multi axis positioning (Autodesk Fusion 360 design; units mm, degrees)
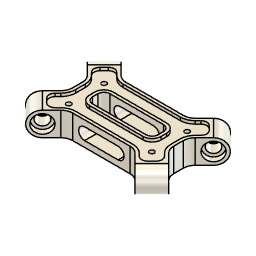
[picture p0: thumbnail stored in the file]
base_feature "Base Feature1" bodies "Screw", "Pull Stud", "Base", "Pull Stud (1)", "Pull Stud (2)", "Pull Stud (3)"
base_feature "Base Feature1"
base_feature "Base Feature1"
as_built_joint "As-built1"
as_built_joint "As-built4"
as_built_joint "As-built2" OffsetX 0 OffsetY 0 OffsetZ 0 AngleZ 0 DistanceMinimum 0
as_built_joint "As-built3" OffsetX 0 OffsetY 0 OffsetZ 0 AngleZ 0 DistanceMinimum 0
motion_link "MotionLink1" Value1 10 Value2 10
sketch "Stock Top Profile" plane through (0, 0, 0) normal (0, 1, 0) x axis (1, 0, 0)
  line L1 (-76.2, -12.7) -> (76.2, -12.7)
  line L2 (-76.2, 12.7) -> (-76.2, -12.7)
  line L3 (76.2, 12.7) -> (-76.2, 12.7)
  line L4 (76.2, -12.7) -> (76.2, 12.7)
  line L5 (-76.2, 12.7) -> (76.2, -12.7)
  line L6 (76.2, 12.7) -> (-76.2, -12.7)
  point P6 (0, 0)
  point P1 (0, 0)
  point P4 (-76.2, 12.7)
  point P5 (76.2, 12.7)
  point P3 (-76.2, -12.7)
  perpendicular L1 L2
  parallel L1 L3
  parallel L2 L4
  horizontal L1
  coincident L5 P6
  coincident L6 P6
  coincident P1 P6
  dimension "d13" distance P4 P5 = 152.4
  dimension "d14" distance P3 P4 = 25.4
  dimension "d21" OffsetX = 0
  dimension "d22" OffsetY = 0
  dimension "d23" OffsetZ = 0
  dimension "d24" AngleZ = 0
  dimension "d172" OffsetX = 0
  dimension "d173" OffsetY = 0
  dimension "d174" OffsetZ = 0
  dimension "d175" AngleZ = 0
  dimension "d188" OffsetX = 0
  dimension "d189" OffsetY = 0
  dimension "d190" OffsetZ = 0
  dimension "d191" AngleZ = 0
  dimension "d218" OffsetX = 0
  dimension "d219" OffsetY = 0
  dimension "d220" OffsetZ = 0
  dimension "d221" AngleZ = 0
  dimension "d238" OffsetX = 0
  dimension "d239" OffsetY = 0
  dimension "d240" OffsetZ = 0
  dimension "d241" AngleZ = 0
  dimension "d270" OffsetX = 0
  dimension "d271" OffsetY = 0
  dimension "d272" OffsetZ = 0
  dimension "d273" AngleZ = 0
extrude "Extrude1" new body sketch "Stock Top Profile" profile of L1 L2 L3 L4 along normal blind 38.1
sketch "Sketch1" plane through (0, 0, 25.6902) normal (0, 0, 1) x axis (1, 0, 0)
  line L1 (-62.3, 41.746) -> (-62.3, 43.3968)
  line L2 (62.3, 41.746) -> (-62.3, 41.746)
  line L3 (62.3, 43.3968) -> (62.3, 41.746)
  line L4 (-62.3, 43.3968) -> (62.3, 43.3968)
  line L5 (0, 40.3968) -> (0, 43.3968)
  line L6 (-62.3, 40.3968) -> (62.3, 40.3968)
  point P6 (0, 43.3968)
  point P7 (0, 40.3968)
  midpoint L4 P6
  perpendicular L2 L5
  coincident P7 L6
joint_origin "JointOrigin1" OffsetX 0 OffsetY 0 OffsetZ 0 AngleZ 0
joint "Assemble1" alignAngle 0 alignOffsetX 0 alignOffsetY 0 alignOffsetZ 0
joint "Assemble3" alignAngle 0 alignOffsetX 0 alignOffsetY 0 alignOffsetZ 0
sketch "Step Profile" plane through (76.2, 0, 0) normal (1, 0, 0) x axis (0, 0, -1)
  line L1 (12.7, 0) -> (-12.7, 0)
  line L2 (12.7, 38.1) -> (12.7, 0)
  line L3 (-12.7, 38.1) -> (12.7, 38.1)
  line L4 (-12.7, 0) -> (-12.7, 38.1)
  line L5 (-50.8, 38.1) -> (50.8, 38.1)
  line L6 (-50.8, 6.731) -> (-50.8, 38.1)
  line L7 (50.8, 6.731) -> (-50.8, 6.731)
  line L8 (50.8, 38.1) -> (50.8, 6.731)
  line L9 (-50.8, 6.731) -> (50.8, 38.1)
  line L10 (50.8, 6.731) -> (-50.8, 38.1)
  point P10 (0, 22.4155)
  point P1 (0, 0)
  point P6 (50.8, 38.1)
  point P7 (-50.8, 38.1)
  perpendicular L5 L6
  parallel L5 L7
  parallel L6 L8
  horizontal L5
  coincident L9 P10
  coincident L10 P10
  vertical P1 P10
  collinear L3 L5
  dimension "d184" distance P6 P7 = 101.6
  dimension "d185" distance L1 L7 = 6.731
extrude "Extrude2" add sketch "Step Profile" profile of L2 L4 L5 L6 L7 L8 to an object
copy_paste "CutPaste1"
copy_paste "CutPaste2"
copy_paste "CutPaste3"
copy_paste "CutPaste4"
as_built_joint "As-built5"
base_feature "Base Feature1"
joint "Assemble4" alignAngle 0 alignOffsetX 0 alignOffsetY 0 alignOffsetZ 0
copy_paste "CutPaste5"
base_feature "Base Feature1"
base_feature "Base Feature1" bodies "Pull Stud (1)", "Pull Stud (2)", "Base", "Screw", "Pull Stud (3)", "Pull Stud"
base_feature "Base Feature1"
base_feature "Base Feature1" bodies "Body1"
sketch "Sketch1" plane through (0, 85.85, 0) normal (0, 1, 0) x axis (-1, 0, 0)
  line L1 (62.3776, 12.3492) -> (-62.2224, 12.3492)
  line L2 (62.3776, 14) -> (62.3776, 12.3492)
  line L3 (-62.2224, 14) -> (62.3776, 14)
  line L4 (-62.2224, 12.3492) -> (-62.2224, 14)
  line L5 (62.3776, 11) -> (-62.2224, 11)
  line L6 (62.3776, 3) -> (-62.2224, 3)
joint_origin "JointOrigin1" OffsetX 0 named "d5_1" OffsetY 0 named "d6_1" OffsetZ 0 named "d7_1" AngleZ 0 named "d8_1"
joint_origin "JointOrigin2" OffsetX 0 named "d9_1" OffsetY 0 named "d10_1" OffsetZ 0 named "d11_1" AngleZ 0 named "d12_1"
copy_paste "CopyPaste1"
as_built_joint "As-built1"
as_built_joint "As-built2"
as_built_joint "As-built3" OffsetX 0 named "d13_1" OffsetY 0 named "d14_1" OffsetZ 0 named "d15_1" AngleZ 0 named "d16_1"
as_built_joint "As-built4" OffsetX 0 named "d17_1" OffsetY 0 named "d18_1" OffsetZ 0 named "d19_1" AngleZ 0 named "d20_1"
motion_link "MotionLink1" Value1 10 named "d21_1" Value2 10 named "d22_1"
sketch "Sketch1" plane through (0, 0, 0) normal (0, 1, 0) x axis (1, 0, 0)
  line L1 (-95.25, -50.8) -> (95.25, -50.8)
  line L2 (-95.25, 50.8) -> (-95.25, -50.8)
  line L3 (95.25, 50.8) -> (-95.25, 50.8)
  line L4 (95.25, -50.8) -> (95.25, 50.8)
  line L5 (-95.25, 50.8) -> (95.25, -50.8)
  line L6 (95.25, 50.8) -> (-95.25, -50.8)
  point P6 (0, 0)
  point P1 (0, 0)
  point P4 (-95.25, 50.8)
  point P5 (95.25, 50.8)
  point P3 (-95.25, -50.8)
  perpendicular L1 L2
  parallel L1 L3
  parallel L2 L4
  horizontal L1
  coincident L5 P6
  coincident L6 P6
  coincident P1 P6
  dimension "d23_1" distance P4 P5 = 190.5
  dimension "d24_1" distance P3 P4 = 101.6
extrude "Extrude1" new body sketch "Sketch1" profile of L1 L2 L3 L4 along normal blind 50.8 named "d25_1"
position "Position2"
joint "Assemble1" alignAngle 180 alignOffsetX 0 alignOffsetY 0 alignOffsetZ 0
joint "Assemble2" alignAngle 0 alignOffsetX 0 alignOffsetY 0 named "d41_1" alignOffsetZ 0 named "d42_1"
joint "Assemble10" OffsetX 0 OffsetY 0 OffsetZ 0 AngleZ 0 alignAngle 0 alignOffsetX 0 alignOffsetY 0 alignOffsetZ 0
sketch "Stock Top Profile" plane through (0, 0, 0) normal (0, 1, 0) x axis (1, 0, 0)
  line L1 (-76.2, -12.7) -> (76.2, -12.7)
  line L2 (-76.2, 12.7) -> (-76.2, -12.7)
  line L3 (76.2, 12.7) -> (-76.2, 12.7)
  line L4 (76.2, -12.7) -> (76.2, 12.7)
  line L5 (-76.2, 12.7) -> (76.2, -12.7)
  line L6 (76.2, 12.7) -> (-76.2, -12.7)
  point P6 (0, 0)
  point P1 (0, 0)
  point P4 (-76.2, 12.7)
  point P5 (76.2, 12.7)
  point P3 (-76.2, -12.7)
  perpendicular L1 L2
  parallel L1 L3
  parallel L2 L4
  horizontal L1
  coincident L5 P6
  coincident L6 P6
  coincident P1 P6
  dimension "d13_2" distance P4 P5 = 152.4
  dimension "d14_2" distance P3 P4 = 25.4
  dimension "d21_2" OffsetX = 0
  dimension "d22_2" OffsetY = 0
  dimension "d23_2" OffsetZ = 0
  dimension "d24_2" AngleZ = 0
  dimension "d172_1" OffsetX = 0
  dimension "d173_1" OffsetY = 0
  dimension "d174_1" OffsetZ = 0
  dimension "d175_1" AngleZ = 0
  dimension "d188_1" OffsetX = 0
  dimension "d189_1" OffsetY = 0
  dimension "d190_1" OffsetZ = 0
  dimension "d191_1" AngleZ = 0
  dimension "d218_1" OffsetX = 0
  dimension "d219_1" OffsetY = 0
  dimension "d220_1" OffsetZ = 0
  dimension "d221_1" AngleZ = 0
  dimension "d238_1" OffsetX = 0
  dimension "d239_1" OffsetY = 0
  dimension "d240_1" OffsetZ = 0
  dimension "d241_1" AngleZ = 0
  dimension "d270_1" OffsetX = 0
  dimension "d271_1" OffsetY = 0
  dimension "d272_1" OffsetZ = 0
  dimension "d273_1" AngleZ = 0
extrude "Extrude1" new body sketch "Stock Top Profile" profile of L1 L2 L3 L4 along normal blind 38.1 named "d15_2"
position "Position4"
position "Position5"
joint_origin "JointOrigin3" OffsetX 0 named "d41_2" OffsetY 0 named "d42_2" OffsetZ 0 named "d43_1" AngleZ 0 named "d44_1"
joint_origin "JointOrigin4" OffsetX 0 named "d49_1" OffsetY 0 named "d50_1" OffsetZ 0 named "d51_1" AngleZ 0 named "d52_1"
sketch "Step Profile" plane through (76.2, 0, 0) normal (1, 0, 0) x axis (0, 0, -1)
  line L1 (12.7, 0) -> (-12.7, 0)
  line L2 (12.7, 38.1) -> (12.7, 0)
  line L3 (-12.7, 38.1) -> (12.7, 38.1)
  line L4 (-12.7, 0) -> (-12.7, 38.1)
  line L5 (-50.8, 38.1) -> (50.8, 38.1)
  line L6 (-50.8, 6.731) -> (-50.8, 38.1)
  line L7 (50.8, 6.731) -> (-50.8, 6.731)
  line L8 (50.8, 38.1) -> (50.8, 6.731)
  line L9 (-50.8, 6.731) -> (50.8, 38.1)
  line L10 (50.8, 6.731) -> (-50.8, 38.1)
  point P10 (0, 22.4155)
  point P1 (0, 0)
  point P6 (50.8, 38.1)
  point P7 (-50.8, 38.1)
  perpendicular L5 L6
  parallel L5 L7
  parallel L6 L8
  horizontal L5
  coincident L9 P10
  coincident L10 P10
  vertical P1 P10
  collinear L3 L5
  dimension "d184_1" distance P6 P7 = 101.6
  dimension "d185_1" distance L1 L7 = 6.731
extrude "Extrude2" add sketch "Step Profile" profile of L2 L4 L5 L6 L7 L8 to an object
joint_origin "JointOrigin13" OffsetX 0 named "d262_1" OffsetY 0 named "d263_1" OffsetZ 0 named "d264_1" AngleZ 0 named "d265_1"
as_built_joint "As-built6"
sketch "Sketch3" plane through (0, 38.1, 0) normal (0, 1, 0) x axis (-1, 0, 0)
  line L1 (76.2, 50.8) -> (76.2, -50.8)
  line L2 (-76.2, 50.8) -> (76.2, 50.8)
  line L3 (-76.2, -50.8) -> (-76.2, 50.8)
  line L4 (76.2, -50.8) -> (-76.2, -50.8)
  line L5 (-76.2, -32.8395) -> (-58.2395, -50.8)
  line L6 (-53.7494, -10.3888) -> (-76.2, -32.8395)
  line L7 (-35.7888, -28.3494) -> (-58.2395, -50.8)
  line L8 (-25.2088, 0) -> (0, 0)
  line L9 (-53.7494, 0) -> (-53.7494, -10.3888)
  line L10 (9.7506, -28.3494) -> (-35.7888, -28.3494)
  line L11 (25.4, -12.7) -> (9.7506, -28.3494)
  line L12 (76.2, -12.7) -> (25.4, -12.7)
  line L13 (76.2, 0) -> (76.2, -12.7)
  line L14 (76.2, 0) -> (76.2, 12.7)
  line L15 (76.2, 12.7) -> (25.4, 12.7)
  line L16 (25.4, 12.7) -> (9.7506, 28.3494)
  line L17 (9.7506, 28.3494) -> (-35.7888, 28.3494)
  line L18 (-35.7888, 28.3494) -> (-58.2395, 50.8)
  line L19 (-76.2, 32.8395) -> (-58.2395, 50.8)
  line L20 (-53.7494, 10.3888) -> (-76.2, 32.8395)
  line L21 (-53.7494, 0) -> (-53.7494, 10.3888)
  line L22 (0, -18.5532) -> (0, 0)
  line L23 (35.7888, -28.3494) -> (58.2395, -50.8)
  line L24 (76.2, -32.8395) -> (58.2395, -50.8)
  line L25 (53.7494, -10.3888) -> (76.2, -32.8395)
  line L26 (53.7494, 0) -> (53.7494, -10.3888)
  line L27 (53.7494, 0) -> (53.7494, 10.3888)
  line L28 (53.7494, 10.3888) -> (76.2, 32.8395)
  line L29 (76.2, 32.8395) -> (58.2395, 50.8)
  line L30 (35.7888, 28.3494) -> (58.2395, 50.8)
  line L31 (9.7506, -28.3494) -> (35.7888, -28.3494)
  line L32 (9.7506, 28.3494) -> (35.7888, 28.3494)
  point P6 (-58.2395, -50.8)
  point P7 (-76.2, -32.8395)
  point P1 (0, 0)
  point P10 (0, 0)
  point P11 (-25.2088, 0)
  point P12 (-53.7494, 0)
  point P15 (76.2, -12.7)
  point P16 (76.2, 0)
  point P22 (-58.2395, 50.8)
  point P23 (-76.2, 32.8395)
  point P8 (-53.7494, -10.3888)
  point P24 (-53.7494, 10.3888)
  point P9 (-35.7888, -28.3494)
  point P21 (-35.7888, 28.3494)
  point P25 (-53.7494, 0)
  point P13 (9.7506, -28.3494)
  point P20 (9.7506, 28.3494)
  point P14 (25.4, -12.7)
  point P19 (25.4, 12.7)
  point P17 (76.2, 12.7)
  point P18 (76.2, 0)
  point P26 (0, 0)
  point P28 (58.2395, -50.8)
  point P30 (76.2, -32.8395)
  point P31 (53.7494, -10.3888)
  point P29 (35.7888, -28.3494)
  point P32 (53.7494, 0)
  point P37 (35.7888, 28.3494)
  point P36 (58.2395, 50.8)
  point P35 (76.2, 32.8395)
  point P33 (53.7494, 10.3888)
  point P34 (53.7494, 0)
  coincident L4 P6
  coincident L3 P7
  perpendicular L5 L6
  perpendicular L5 L7
  coincident P1 P10
  horizontal L8
  equal L6 L7
  perpendicular L8 L9
  horizontal P11 P12
  horizontal L10
  parallel L7 L11
  coincident L1 P15
  perpendicular L1 L12
  midpoint L1 P16
  symmetric P6 L8 P22
  symmetric P7 L8 P23
  symmetric P8 L8 P24
  symmetric P9 L8 P21
  symmetric L8 P12 P25
  symmetric L8 P13 P20
  symmetric L8 P14 P19
  symmetric L8 P15 P17
  symmetric L8 P16 P18
  coincident P1 P26
  perpendicular L8 L22
  symmetric P6 L22 P28
  symmetric P7 L22 P30
  symmetric P8 L22 P31
  symmetric P9 L22 P29
  symmetric P12 L22 P32
  symmetric P21 L22 P37
  symmetric P22 L22 P36
  symmetric P23 L22 P35
  symmetric P24 L22 P33
  symmetric P25 L22 P34
  dimension "d335" angle L4 L5 = 45
  dimension "d336" distance P6 P7 = 25.4
  dimension "d337" distance P7 P8 = 31.75
  dimension "d338" distance P15 P16 = 12.7
  dimension "d339" distance P14 P15 = 50.8
extrude "Extrude3" cut sketch "Sketch3" profile of L1 L2 L3 L4 L5 L6 L7 L9 L10 L12 L13 L14 L15 L17 L18 L19 L20 L21 L23 L24 L25 L26 L27 L28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 no distance stored
split "Split1"
remove_body "RemoveBody1"
offset_faces "OffsetFaces1" distance -5.969
fillet "Fillet1" radius 12.7
fillet "Fillet2" radius 12.7
sketch "Sketch5" plane through (3.7197, 0, -3.7197) normal (-0.7071, 0, 0.7071) x axis (0.7071, 0, 0.7071)
  line L1 (64.4026, 12.7) -> (50.6131, 12.7)
  line L2 (50.6131, 38.1) -> (64.4026, 38.1)
  line L3 (53.7881, 15.875) -> (53.7881, 34.925)
  line L4 (64.4026, 15.875) -> (53.7881, 15.875)
  line L5 (53.7881, 34.925) -> (64.4026, 34.925)
  line L6 (50.6131, 12.7) -> (50.6131, 38.1)
  arc A1 centre (64.4026, 25.4) radius 12.7 clockwise from (64.4026, 38.1) to (64.4026, 12.7)
  circle C1 centre (64.4026, 25.4) radius 6.35
  arc A2 centre (64.4026, 25.4) radius 9.525 clockwise from (64.4026, 34.925) to (64.4026, 15.875)
  arc A3 centre (64.4026, 25.4) radius 9.525 clockwise from (64.4026, 15.875) to (64.4026, 34.925)
  concentric A1 C1
  tangent L4 A3
  parallel L1 L4
  concentric A1 A2
  parallel L2 L5
  tangent A2 L5
  tangent L4 A2
  dimension "d346" diameter C1 = 12.7
extrude "Extrude4" cut sketch "Sketch5" profile of C1 no distance stored
extrude "Extrude5" cut sketch "Sketch5" profile of C1 A2 A3 against normal blind 6.35
work_plane "WorkPlane1"
mirror "Mirror1"
mirror "Mirror2"
mirror "Mirror3"
sketch "Sketch10" plane through (0, 38.1, 0) normal (0, 1, 0) x axis (-1, 0, 0)
  line L1 (67.2197, -23.8592) -> (49.2592, -41.8197)
  line L2 (57.4691, -14.1086) -> (67.2197, -23.8592)
  line L3 (53.7494, 5.1283) -> (53.7494, -5.1283)
  line L4 (67.2197, 23.8592) -> (57.4691, 14.1086)
  line L5 (49.2592, 41.8197) -> (67.2197, 23.8592)
  line L6 (39.5086, 32.0691) -> (49.2592, 41.8197)
  line L7 (-30.5283, 28.3494) -> (30.5283, 28.3494)
  line L8 (-49.2592, 41.8197) -> (-39.5086, 32.0691)
  line L9 (-67.2197, 23.8592) -> (-49.2592, 41.8197)
  line L10 (-57.4691, 14.1086) -> (-67.2197, 23.8592)
  line L11 (-53.7494, -5.1283) -> (-53.7494, 5.1283)
  line L12 (-67.2197, -23.8592) -> (-57.4691, -14.1086)
  line L13 (-49.2592, -41.8197) -> (-67.2197, -23.8592)
  line L14 (-39.5086, -32.0691) -> (-49.2592, -41.8197)
  line L15 (30.5283, -28.3494) -> (-30.5283, -28.3494)
  line L16 (49.2592, -41.8197) -> (39.5086, -32.0691)
  line L17 (34.925, -9.2994) -> (-34.925, -9.2994)
  line L18 (34.925, 9.2994) -> (34.925, -9.2994)
  line L19 (-34.925, 9.2994) -> (34.925, 9.2994)
  line L20 (-34.925, -9.2994) -> (-34.925, 9.2994)
  line L21 (34.925, 9.2994) -> (-34.925, -9.2994)
  line L22 (-34.925, 9.2994) -> (34.925, -9.2994)
  arc A1 centre (66.4494, -5.1283) radius 12.7 clockwise from (57.4691, -14.1086) to (53.7494, -5.1283)
  arc A2 centre (66.4494, 5.1283) radius 12.7 clockwise from (53.7494, 5.1283) to (57.4691, 14.1086)
  arc A3 centre (30.5283, 41.0494) radius 12.7 clockwise from (39.5086, 32.0691) to (30.5283, 28.3494)
  arc A4 centre (-30.5283, 41.0494) radius 12.7 clockwise from (-30.5283, 28.3494) to (-39.5086, 32.0691)
  arc A5 centre (-66.4494, 5.1283) radius 12.7 clockwise from (-57.4691, 14.1086) to (-53.7494, 5.1283)
  arc A6 centre (-66.4494, -5.1283) radius 12.7 clockwise from (-53.7494, -5.1283) to (-57.4691, -14.1086)
  arc A7 centre (-30.5283, -41.0494) radius 12.7 clockwise from (-39.5086, -32.0691) to (-30.5283, -28.3494)
  arc A8 centre (30.5283, -41.0494) radius 12.7 clockwise from (30.5283, -28.3494) to (39.5086, -32.0691)
  point P38 (0, 0)
  point P1 (0, 0)
  point P34 (-34.925, -9.2994)
  point P35 (34.925, -9.2994)
  perpendicular L17 L18
  parallel L17 L19
  parallel L18 L20
  horizontal L17
  coincident L21 P38
  coincident L22 P38
  coincident P1 P38
  dimension "d373" distance L15 L17 = 19.05
  dimension "d374" distance P34 P35 = 69.85
extrude "Extrude11" cut sketch "Sketch10" profile of L17 L18 L19 L20 no distance stored
fillet "Fillet6" radius 6.35
sketch "Sketch11" plane through (0, 38.1, 0) normal (0, 1, 0) x axis (-1, 0, 0)
  line L1 (28.575, 9.2994) -> (-28.575, 9.2994)
  line L2 (34.925, -2.9494) -> (34.925, 2.9494)
  line L3 (-28.575, -9.2994) -> (28.575, -9.2994)
  line L4 (-34.925, 2.9494) -> (-34.925, -2.9494)
  line L5 (67.2197, -23.8592) -> (49.2592, -41.8197)
  line L6 (57.4691, -14.1086) -> (67.2197, -23.8592)
  line L7 (53.7494, 5.1283) -> (53.7494, -5.1283)
  line L8 (67.2197, 23.8592) -> (57.4691, 14.1086)
  line L9 (49.2592, 41.8197) -> (67.2197, 23.8592)
  line L10 (39.5086, 32.0691) -> (49.2592, 41.8197)
  line L11 (-30.5283, 28.3494) -> (30.5283, 28.3494)
  line L12 (-49.2592, 41.8197) -> (-39.5086, 32.0691)
  line L13 (-67.2197, 23.8592) -> (-49.2592, 41.8197)
  line L14 (-57.4691, 14.1086) -> (-67.2197, 23.8592)
  line L15 (-53.7494, -5.1283) -> (-53.7494, 5.1283)
  line L16 (-67.2197, -23.8592) -> (-57.4691, -14.1086)
  line L17 (-49.2592, -41.8197) -> (-67.2197, -23.8592)
  line L18 (-39.5086, -32.0691) -> (-49.2592, -41.8197)
  line L19 (30.5283, -28.3494) -> (-30.5283, -28.3494)
  line L20 (49.2592, -41.8197) -> (39.5086, -32.0691)
  line L21 (30.5283, -25.1744) -> (-30.5283, -25.1744)
  line L22 (49.2592, -37.3296) -> (41.7537, -29.824)
  line L23 (62.7296, -23.8592) -> (49.2592, -37.3296)
  line L24 (55.224, -16.3537) -> (62.7296, -23.8592)
  line L25 (50.5744, 5.1283) -> (50.5744, -5.1283)
  line L26 (62.7296, 23.8592) -> (55.224, 16.3537)
  line L27 (49.2592, 37.3296) -> (62.7296, 23.8592)
  line L28 (41.7537, 29.824) -> (49.2592, 37.3296)
  line L29 (-30.5283, 25.1744) -> (30.5283, 25.1744)
  line L30 (-49.2592, 37.3296) -> (-41.7537, 29.824)
  line L31 (-62.7296, 23.8592) -> (-49.2592, 37.3296)
  line L32 (-55.224, 16.3537) -> (-62.7296, 23.8592)
  line L33 (-50.5744, -5.1283) -> (-50.5744, 5.1283)
  line L34 (-62.7296, -23.8592) -> (-55.224, -16.3537)
  line L35 (-49.2592, -37.3296) -> (-62.7296, -23.8592)
  line L36 (-41.7537, -29.824) -> (-49.2592, -37.3296)
  line L37 (-28.575, -12.4744) -> (28.575, -12.4744)
  line L38 (38.1, -2.9494) -> (38.1, 2.9494)
  line L39 (28.575, 12.4744) -> (-28.575, 12.4744)
  line L40 (-38.1, 2.9494) -> (-38.1, -2.9494)
  arc A1 centre (28.575, 2.9494) radius 6.35 clockwise from (28.575, 9.2994) to (34.925, 2.9494)
  arc A2 centre (28.575, -2.9494) radius 6.35 clockwise from (34.925, -2.9494) to (28.575, -9.2994)
  arc A3 centre (-28.575, -2.9494) radius 6.35 clockwise from (-28.575, -9.2994) to (-34.925, -2.9494)
  arc A4 centre (-28.575, 2.9494) radius 6.35 clockwise from (-34.925, 2.9494) to (-28.575, 9.2994)
  arc A5 centre (66.4494, -5.1283) radius 12.7 clockwise from (57.4691, -14.1086) to (53.7494, -5.1283)
  arc A6 centre (66.4494, 5.1283) radius 12.7 clockwise from (53.7494, 5.1283) to (57.4691, 14.1086)
  arc A7 centre (30.5283, 41.0494) radius 12.7 clockwise from (39.5086, 32.0691) to (30.5283, 28.3494)
  arc A8 centre (-30.5283, 41.0494) radius 12.7 clockwise from (-30.5283, 28.3494) to (-39.5086, 32.0691)
  arc A9 centre (-66.4494, 5.1283) radius 12.7 clockwise from (-57.4691, 14.1086) to (-53.7494, 5.1283)
  arc A10 centre (-66.4494, -5.1283) radius 12.7 clockwise from (-53.7494, -5.1283) to (-57.4691, -14.1086)
  arc A11 centre (-30.5283, -41.0494) radius 12.7 clockwise from (-39.5086, -32.0691) to (-30.5283, -28.3494)
  arc A12 centre (30.5283, -41.0494) radius 12.7 clockwise from (30.5283, -28.3494) to (39.5086, -32.0691)
  arc A13 centre (30.5283, -41.0494) radius 15.875 clockwise from (30.5283, -25.1744) to (41.7537, -29.824)
  arc A14 centre (66.4494, -5.1283) radius 15.875 clockwise from (55.224, -16.3537) to (50.5744, -5.1283)
  arc A15 centre (66.4494, 5.1283) radius 15.875 clockwise from (50.5744, 5.1283) to (55.224, 16.3537)
  arc A16 centre (30.5283, 41.0494) radius 15.875 clockwise from (41.7537, 29.824) to (30.5283, 25.1744)
  arc A17 centre (-30.5283, 41.0494) radius 15.875 clockwise from (-30.5283, 25.1744) to (-41.7537, 29.824)
  arc A18 centre (-66.4494, 5.1283) radius 15.875 clockwise from (-55.224, 16.3537) to (-50.5744, 5.1283)
  arc A19 centre (-66.4494, -5.1283) radius 15.875 clockwise from (-50.5744, -5.1283) to (-55.224, -16.3537)
  arc A20 centre (-30.5283, -41.0494) radius 15.875 clockwise from (-41.7537, -29.824) to (-30.5283, -25.1744)
  arc A21 centre (-28.575, -2.9494) radius 9.525 clockwise from (-28.575, -12.4744) to (-38.1, -2.9494)
  arc A22 centre (28.575, -2.9494) radius 9.525 clockwise from (38.1, -2.9494) to (28.575, -12.4744)
  arc A23 centre (28.575, 2.9494) radius 9.525 clockwise from (28.575, 12.4744) to (38.1, 2.9494)
  arc A24 centre (-28.575, 2.9494) radius 9.525 clockwise from (-38.1, 2.9494) to (-28.575, 12.4744)
  dimension "d377" = 3.175
  dimension "d378" = -3.175
extrude "Extrude12" cut sketch "Sketch11" profile of L28 A15 L21 L22 L25 A13 L23 L24 L32 L26 A14 L27 A16 L29 A17 L30 L31 A18 L33 A19 L34 L35 L36 A20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 against normal blind 3.175
fillet "Fillet7" radius 6.35
work_plane "WorkPlane2"
mirror "Mirror4"
sketch "Sketch12" plane through (0, 0, 28.3494) normal (0, 0, 1) x axis (1, 0, 0)
  line L1 (-30.5283, 12.7) -> (-30.5283, 38.1)
  line L2 (30.5283, 12.7) -> (-30.5283, 12.7)
  line L3 (30.5283, 38.1) -> (30.5283, 12.7)
  line L4 (-30.5283, 38.1) -> (30.5283, 38.1)
  line L5 (24.1783, 19.05) -> (-24.1783, 19.05)
  line L6 (24.1783, 31.75) -> (24.1783, 19.05)
  line L7 (-24.1783, 31.75) -> (24.1783, 31.75)
  line L8 (-24.1783, 19.05) -> (-24.1783, 31.75)
  dimension "d383" = -6.35
extrude "Extrude13" cut sketch "Sketch12" profile of L8 L5 L6 L7 no distance stored
fillet "Fillet8" radius 6.35
sketch "Sketch13" plane through (0, 34.925, 0) normal (0, 1, 0) x axis (-1, 0, 0)
  line L1 (-28.575, -12.4744) -> (28.575, -12.4744)
  line L2 (-38.1, 2.9494) -> (-38.1, -2.9494)
  line L3 (28.575, 12.4744) -> (-28.575, 12.4744)
  line L4 (38.1, -2.9494) -> (38.1, 2.9494)
  line L5 (-58.2395, 28.3494) -> (-53.7494, 32.8395)
  line L6 (-55.224, 16.3537) -> (-58.2395, 19.3691)
  line L7 (-50.5744, -5.1283) -> (-50.5744, 5.1283)
  line L8 (-58.2395, -19.3691) -> (-55.224, -16.3537)
  line L9 (-53.7494, -32.8395) -> (-58.2395, -28.3494)
  line L10 (-41.7537, -29.824) -> (-44.7691, -32.8395)
  line L11 (30.5283, -25.1744) -> (-30.5283, -25.1744)
  line L12 (44.7691, -32.8395) -> (41.7537, -29.824)
  line L13 (58.2395, -28.3494) -> (53.7494, -32.8395)
  line L14 (55.224, -16.3537) -> (58.2395, -19.3691)
  line L15 (50.5744, 5.1283) -> (50.5744, -5.1283)
  line L16 (58.2395, 19.3691) -> (55.224, 16.3537)
  line L17 (53.7494, 32.8395) -> (58.2395, 28.3494)
  line L18 (41.7537, 29.824) -> (44.7691, 32.8395)
  line L19 (-30.5283, 25.1744) -> (30.5283, 25.1744)
  line L20 (-44.7691, 32.8395) -> (-41.7537, 29.824)
  line L21 (36.6034, -26.3828) -> (51.7828, -11.2034)
  arc A1 centre (28.575, -2.9494) radius 9.525 clockwise from (38.1, -2.9494) to (28.575, -12.4744)
  arc A2 centre (-28.575, -2.9494) radius 9.525 clockwise from (-28.575, -12.4744) to (-38.1, -2.9494)
  arc A3 centre (-28.575, 2.9494) radius 9.525 clockwise from (-38.1, 2.9494) to (-28.575, 12.4744)
  arc A4 centre (28.575, 2.9494) radius 9.525 clockwise from (28.575, 12.4744) to (38.1, 2.9494)
  arc A5 centre (-49.2592, 28.3494) radius 6.35 clockwise from (-53.7494, 32.8395) to (-44.7691, 32.8395)
  arc A6 centre (-53.7494, 23.8592) radius 6.35 clockwise from (-58.2395, 19.3691) to (-58.2395, 28.3494)
  arc A7 centre (-66.4494, 5.1283) radius 15.875 clockwise from (-55.224, 16.3537) to (-50.5744, 5.1283)
  arc A8 centre (-66.4494, -5.1283) radius 15.875 clockwise from (-50.5744, -5.1283) to (-55.224, -16.3537)
  arc A9 centre (-53.7494, -23.8592) radius 6.35 clockwise from (-58.2395, -28.3494) to (-58.2395, -19.3691)
  arc A10 centre (-49.2592, -28.3494) radius 6.35 clockwise from (-44.7691, -32.8395) to (-53.7494, -32.8395)
  arc A11 centre (-30.5283, -41.0494) radius 15.875 clockwise from (-41.7537, -29.824) to (-30.5283, -25.1744)
  arc A12 centre (30.5283, -41.0494) radius 15.875 clockwise from (30.5283, -25.1744) to (41.7537, -29.824)
  arc A13 centre (49.2592, -28.3494) radius 6.35 clockwise from (53.7494, -32.8395) to (44.7691, -32.8395)
  arc A14 centre (53.7494, -23.8592) radius 6.35 clockwise from (58.2395, -19.3691) to (58.2395, -28.3494)
  arc A15 centre (66.4494, -5.1283) radius 15.875 clockwise from (55.224, -16.3537) to (50.5744, -5.1283)
  arc A16 centre (66.4494, 5.1283) radius 15.875 clockwise from (50.5744, 5.1283) to (55.224, 16.3537)
  arc A17 centre (53.7494, 23.8592) radius 6.35 clockwise from (58.2395, 28.3494) to (58.2395, 19.3691)
  arc A18 centre (49.2592, 28.3494) radius 6.35 clockwise from (44.7691, 32.8395) to (53.7494, 32.8395)
  arc A19 centre (30.5283, 41.0494) radius 15.875 clockwise from (41.7537, 29.824) to (30.5283, 25.1744)
  arc A20 centre (-30.5283, 41.0494) radius 15.875 clockwise from (-30.5283, 25.1744) to (-41.7537, 29.824)
  circle C1 centre (44.1931, -18.7931) radius 2.5527
  point P63 (51.7828, -11.2034)
  point P64 (36.6034, -26.3828)
  point P62 (44.1931, -18.7931)
  midpoint A15 P63
  midpoint A12 P64
  midpoint P62 L21
  dimension "d386" diameter C1 = 5.1054
extrude "Extrude14" cut sketch "Sketch13" profile of C1 no distance stored
mirror "Mirror5"
mirror "Mirror6"
sketch "2D contour Outside" plane through (0, 38.1, 0) normal (0, 1, 0) x axis (-1, 0, 0)
  line L1 (57.4691, -14.1086) -> (67.2197, -23.8592)
  line L2 (53.7494, 5.1283) -> (53.7494, -5.1283)
  line L3 (67.2197, 23.8592) -> (57.4691, 14.1086)
  line L4 (39.5086, 32.0691) -> (49.2592, 41.8197)
  line L5 (-30.5283, 28.3494) -> (30.5283, 28.3494)
  line L6 (-49.2592, 41.8197) -> (-39.5086, 32.0691)
  line L7 (-57.4691, 14.1086) -> (-67.2197, 23.8592)
  line L8 (-53.7494, -5.1283) -> (-53.7494, 5.1283)
  line L9 (-67.2197, -23.8592) -> (-57.4691, -14.1086)
  line L10 (-39.5086, -32.0691) -> (-49.2592, -41.8197)
  line L11 (30.5283, -28.3494) -> (-30.5283, -28.3494)
  line L12 (49.2592, -41.8197) -> (39.5086, -32.0691)
  line L13 (58.2395, 50.8) -> (49.2592, 41.8197)
  line L14 (67.2197, 23.8592) -> (76.2, 32.8395)
  line L15 (49.2592, -41.8197) -> (58.2395, -50.8)
  line L16 (76.2, -32.8395) -> (67.2197, -23.8592)
  line L17 (-58.2395, -50.8) -> (-49.2592, -41.8197)
  line L18 (-67.2197, -23.8592) -> (-76.2, -32.8395)
  line L19 (-76.2, 32.8395) -> (-67.2197, 23.8592)
  line L20 (-49.2592, 41.8197) -> (-58.2395, 50.8)
  line L21 (76.2, -32.8395) -> (58.2395, -50.8)
  line L22 (58.2395, 50.8) -> (76.2, 32.8395)
  line L23 (-76.2, 32.8395) -> (-58.2395, 50.8)
  line L24 (-76.2, -32.8395) -> (-58.2395, -50.8)
  arc A1 centre (66.4494, -5.1283) radius 12.7 clockwise from (57.4691, -14.1086) to (53.7494, -5.1283)
  arc A2 centre (66.4494, 5.1283) radius 12.7 clockwise from (53.7494, 5.1283) to (57.4691, 14.1086)
  arc A3 centre (30.5283, 41.0494) radius 12.7 clockwise from (39.5086, 32.0691) to (30.5283, 28.3494)
  arc A4 centre (-30.5283, 41.0494) radius 12.7 clockwise from (-30.5283, 28.3494) to (-39.5086, 32.0691)
  arc A5 centre (-66.4494, 5.1283) radius 12.7 clockwise from (-57.4691, 14.1086) to (-53.7494, 5.1283)
  arc A6 centre (-66.4494, -5.1283) radius 12.7 clockwise from (-53.7494, -5.1283) to (-57.4691, -14.1086)
  arc A7 centre (-30.5283, -41.0494) radius 12.7 clockwise from (-39.5086, -32.0691) to (-30.5283, -28.3494)
  arc A8 centre (30.5283, -41.0494) radius 12.7 clockwise from (30.5283, -28.3494) to (39.5086, -32.0691)
  point P38 (58.2395, -50.8)
  point P50 (58.2395, -50.8)
  point P41 (76.2, -32.8395)
  point P51 (76.2, -32.8395)
  point P37 (76.2, 32.8395)
  point P52 (76.2, 32.8395)
  point P35 (58.2395, 50.8)
  point P53 (58.2395, 50.8)
  point P49 (-58.2395, 50.8)
  point P54 (-58.2395, 50.8)
  point P47 (-76.2, 32.8395)
  point P55 (-76.2, 32.8395)
  point P43 (-58.2395, -50.8)
  point P56 (-58.2395, -50.8)
  point P45 (-76.2, -32.8395)
  point P57 (-76.2, -32.8395)
  coincident P38 P50
  coincident P41 P51
  coincident P37 P52
  coincident P35 P53
  coincident P49 P54
  coincident P47 P55
  coincident P43 P56
  coincident P45 P57
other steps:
create_component "CreateComponent1"
create_component "CreateComponent2"
create_component "CreateComponent3"
joint_origin "JointOrigin3" OffsetX 0 OffsetY 0 OffsetZ 0 AngleZ 0
joint_origin "JointOrigin3" OffsetX 0 OffsetY 0 OffsetZ 0 AngleZ 0
joint_origin "JointOrigin4" OffsetX 0 OffsetY 0 OffsetZ 0 AngleZ 0
create_component "CreateComponent5"
create_component "CreateComponent7"
remove_instance "RemoveInstance1"
remove_instance "RemoveInstance2"
remove_instance "RemoveInstance3"
remove_instance "RemoveInstance4"
create_component "CreateComponent8"
joint_origin "JointOrigin1" OffsetX 0 OffsetY 0 OffsetZ 0 AngleZ 0
joint_origin "JointOrigin1" OffsetX 0 OffsetY 0 OffsetZ 0 AngleZ 0
remove_instance "RemoveInstance5"
joint_origin "JointOrigin13" OffsetX 0 OffsetY 0 OffsetZ 0 AngleZ 0
create_component "CreateComponent1"
create_component "CreateComponent2"
create_component "CreateComponent3"
create_component "CreateComponent4"
create_component "CreateComponent5"
joint_origin "JointOrigin1" OffsetX 0 named "d27_1" OffsetY 0 named "d28_1" OffsetZ 0 AngleZ 0
joint_origin "JointOrigin2" OffsetX 0 OffsetY 0 OffsetZ 0 AngleZ 0
create_component "CreateComponent10"
create_component "CreateComponent12"
named bodies: "Screw", "Pull Stud", "Base", "Pull Stud (1)", "Pull Stud (2)", "Pull Stud (3)", "Body1"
